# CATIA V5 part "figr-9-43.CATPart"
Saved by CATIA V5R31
Part number: Part1
Bounding box of the stored display mesh (mm): x -60 to 60, y -70.327 to 65.87, z 0 to 125
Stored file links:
  D:\PROJECTS\Project 2021\US EDITION\CATIA V5 6R 2021\Resources\Part Files\c09_catia_v5_6r2021_prt\c09_catia_v5_6r2021_prt\figr-9-43.CATPart
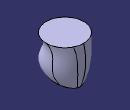
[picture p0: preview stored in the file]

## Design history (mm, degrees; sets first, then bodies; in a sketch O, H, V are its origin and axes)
Set1
  Plane1: type Offset, RefPlane xy-plane, Offset 125
Body1 (main body)
  Sketch1 on xy-plane, origin (0, 0, 0), H (1, 0, 0), V (0, 1, 0)
    ellipse A1 centre (0, 0) semi-axes 50, 30 rotation 270
    point P1 (30, 0)
    coincidence: P1 H, A1 P1
  Sketch2 on Plane1, origin (0, 0, 125), H (1, 0, 0), V (0, 1, 0)
    circle A1 centre (0, 0) radius 60
  Sketch3 on yz-plane, origin (0, 0, 0), H (0, 1, 0), V (0, 0, 1)
    arc A1 centre (-129.6632, 77.2731) radius 195.5761 from (50, 0) to (60, 125) ccw
    point P2 (50, 0)
    point P3 (60, 125)
    reference projected line E1 (-50, 0) -> (50, 0) from edge of Sketch1
    reference projected line E2 (-60, 125) -> (60, 125) from edge of Sketch2
    coincidence: P2 H, P2 E1, P3 E2
  Sketch4 on yz-plane, origin (0, 0, 0), H (0, 1, 0), V (0, 0, 1)
    spline S1 through (-50, 0) (-70, 40) (-50, 100) (-60, 125)
    reference projected line E1 (-60, 125) -> (60, 125) from edge of Sketch2
    reference projected line E2 (-50, 0) -> (50, 0) from edge of Sketch1
    point P1 (-60, 125)
    point P2 (-50, 0)
    coincidence: P1 E1, P2 E2
  Loft1: Sections (Sketch1; Sketch2), Guides (Sketch3; Sketch4)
